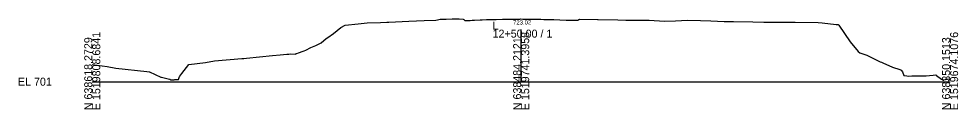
# Model space of a CAD drawing. Extents: x -26 to 3903, y -10 to 9531.
# Drawn here: x -25.7 to 302.8, y 2490.3 to 2522.1 of the extents above; entities that cross this region are included whole.
import ezdxf

# ---------------------------------------------------------------- set-up
doc = ezdxf.new("R2010")
doc.units = 0
for name, color, linetype in [('Default', 7, 'Continuous'), ('Exist Cross Section Cell', 7, 'Continuous'), ('Exist XS Center Line Elevation Label', 7, 'Continuous'), ('Exist XS Ground Line', 7, 'Continuous')]:
    doc.layers.add(name, color=color, linetype=linetype)

msp = doc.modelspace()

# ---------------------------------------------------------------- linework, layer by layer
at = {"layer": 'Exist Cross Section Cell'}
for p, q in [((150, 2500), (150, 2518.27)), ((0, 2500), (150, 2500)), ((150, 2500), (300, 2500))]:
    msp.add_line(p, q, dxfattribs=at)
at = {"layer": 'Exist XS Ground Line'}
msp.add_lwpolyline([(0, 2506.09), (5.18, 2505.3), (8.23, 2504.78), (19.05, 2503.54), (19.92, 2503.48), (20.03, 2503.44), (23.95, 2501.63), (24.24, 2501.53), (27.07, 2500.94), (27.12, 2500.86), (27.18, 2500.83), (27.52, 2500.7), (27.62, 2500.68), (28.6, 2500.69), (28.89, 2500.73), (29.86, 2500.76), (30.08, 2500.8), (30.13, 2500.81), (30.53, 2501.77), (30.62, 2501.89), (31.37, 2502.88), (33.74, 2505.99), (39.61, 2506.79), (42.7, 2507.36), (52.27, 2508.11), (52.82, 2508.14), (52.96, 2508.15), (53.03, 2508.15), (53.06, 2508.15), (53.94, 2508.25), (63.03, 2509.14), (65.73, 2509.42), (68.06, 2509.7), (68.75, 2509.72), (69.26, 2509.76), (71.02, 2509.64), (71.27, 2509.87), (71.49, 2509.95), (72.15, 2510.14), (73.79, 2510.74), (74.06, 2510.78), (74.64, 2511.08), (76.42, 2512.02), (78.21, 2512.76), (80.04, 2513.59), (81.83, 2515.13), (82.33, 2515.46), (84.32, 2516.89), (86.98, 2519.03), (88.42, 2519.89), (93.02, 2520.33), (96.16, 2520.7), (100.82, 2520.82), (102.99, 2520.88), (103.76, 2520.92), (110.76, 2521.29), (116.02, 2521.47), (120.14, 2521.63), (120.79, 2521.77), (121.7, 2521.92), (123.77, 2521.95), (125.84, 2522.09), (128.26, 2522.11), (129.72, 2521.97), (129.93, 2521.79), (130.3, 2521.46), (130.73, 2521.48), (132.17, 2521.52), (132.87, 2521.57), (133.08, 2521.58), (133.68, 2521.61), (135.62, 2521.69), (136.37, 2521.73), (137.86, 2521.78), (138.42, 2521.8), (139.4, 2521.84), (139.52, 2521.85), (139.54, 2521.85), (141.21, 2521.87), (143.43, 2521.93), (144, 2521.94), (144.58, 2521.95), (146.78, 2521.98), (148.97, 2522.01), (149.53, 2522.01), (149.82, 2522.02), (150.59, 2522.01), (152.4, 2521.98), (154.58, 2521.94), (155.19, 2521.93), (156.83, 2521.9), (157.98, 2521.88), (159.15, 2521.85), (159.98, 2521.84), (160.55, 2521.82), (160.78, 2521.81), (161.43, 2521.79), (163.56, 2521.73), (165.69, 2521.65), (166.34, 2521.62), (167.39, 2521.59), (167.98, 2521.58), (169.29, 2521.56), (169.79, 2521.55), (170.18, 2521.8), (170.52, 2522.01), (176.7, 2521.85), (176.9, 2521.84), (183.75, 2521.69), (186.56, 2521.65), (187.84, 2521.64), (194.8, 2521.61), (200.15, 2521.28), (203.93, 2521.39), (208.22, 2521.59), (212.67, 2521.48), (216.33, 2521.35), (220.97, 2521.17), (224.2, 2521.13), (230.99, 2520.97), (234.84, 2520.95), (235.16, 2520.95), (245.73, 2520.9), (245.77, 2520.9), (245.81, 2520.9), (253.84, 2520.75), (255.26, 2520.64), (260.19, 2520.12), (260.5, 2520.08), (260.63, 2520.07), (260.85, 2520.04), (261.11, 2519.8), (265.1, 2513.96), (267.9, 2510.57), (268.48, 2510.09), (270.9, 2509.26), (273.93, 2507.74), (275.53, 2506.96), (276, 2506.83), (276.45, 2506.61), (279.88, 2505.1), (282.48, 2504.24), (282.67, 2504.18), (282.85, 2504.1), (283.32, 2503.5), (283.79, 2502.2), (284.87, 2502.07), (285.48, 2501.98), (286.58, 2502.06), (289.61, 2502.11), (291.6, 2502.09), (292.84, 2502.17), (294.03, 2502.24), (295, 2502.41), (295.28, 2502.13), (296.99, 2500.91), (297.04, 2500.89), (297.24, 2500.86), (297.26, 2500.82), (297.37, 2500.65), (297.76, 2500.69), (298.34, 2500.77), (298.58, 2500.87), (298.67, 2500.87), (299.06, 2500.91), (300, 2500.98)], dxfattribs=at)

# ---------------------------------------------------------------- texts
at = {"layer": 'Default'}
msp.add_text('-', height=0.0001, dxfattribs=at).set_placement((0, 2500))
at = {"layer": 'Exist Cross Section Cell'}
for s, p in [('L', (140, 2518.27)), ('12+50.00 / 1', (140, 2515.47)), ('EL 701', (-26, 2498.6))]:
    msp.add_text(s, height=2.8, dxfattribs=at).set_placement(p)
for s, p in [('E 1519808.6841', (2.8, 2490)), ('E 1519741.3958', (152.8, 2490)), ('E 1519674.1076', (302.8, 2490)), ('N 638618.2729', (0, 2490)), ('N 638484.2121', (150, 2490)), ('N 638350.1513', (300, 2490))]:
    msp.add_text(s, height=2.8, rotation=90, dxfattribs=at).set_placement(p)
at = {"layer": 'Exist XS Center Line Elevation Label'}
msp.add_text('723.02', height=1.5, rotation=0.8401, dxfattribs=at).set_placement((147.18, 2520.01))

doc.saveas('drawing.dxf')
